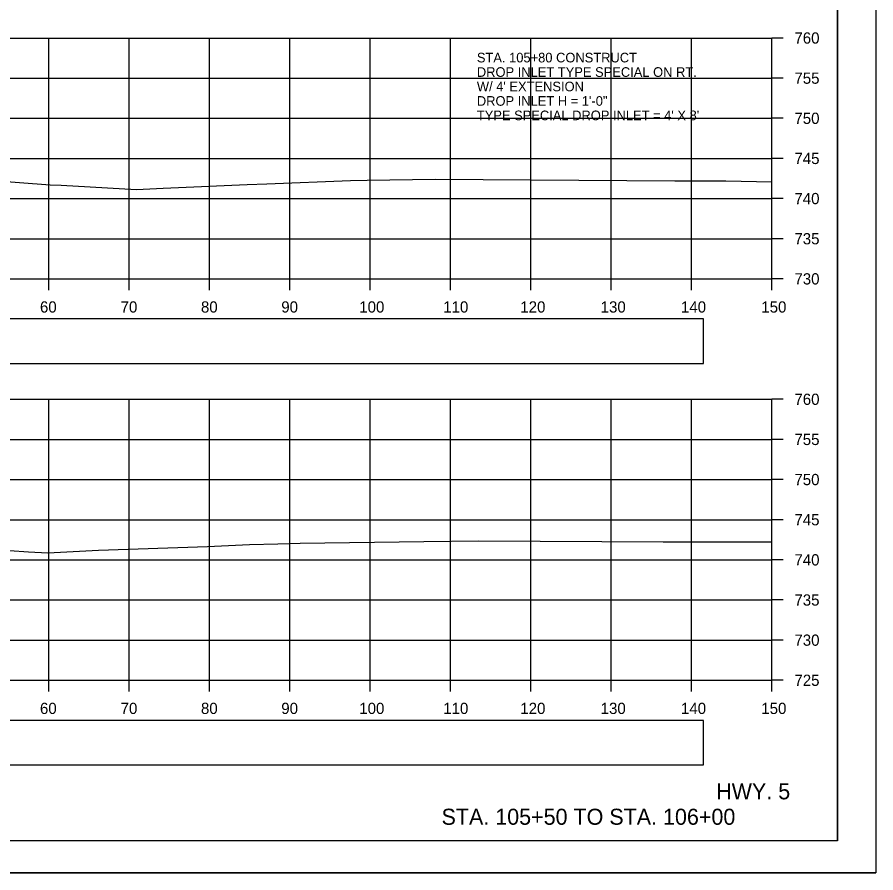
# Model space of a CAD drawing. Extents: x 1202951 to 1376887, y 378065 to 728038.
# Drawn here: x 1376640.7 to 1376747.6, y 379474.5 to 379581.1 of the extents above; entities that cross this region are included whole.
import ezdxf

# ---------------------------------------------------------------- set-up
doc = ezdxf.new("R2010")
doc.units = 0
for name, color, linetype in [('R_Alt Surface', 7, 'Continuous'), ('R_Axis', 7, 'Continuous'), ('R_Axis Annot', 7, 'Continuous'), ('R_Border', 7, 'Continuous'), ('R_Draft', 7, 'Continuous'), ('R_Exist Surface', 7, 'Continuous'), ('R_Grid', 7, 'Continuous'), ('R_No Plot', 7, 'Continuous'), ('R_Water Annot', 7, 'Continuous')]:
    doc.layers.add(name, color=color, linetype=linetype)

msp = doc.modelspace()

# ---------------------------------------------------------------- linework, layer by layer
at = {"layer": 'R_Alt Surface'}
for points in [[(1376615.43, 379537.98), (1376726.14, 379537.98), (1376726.14, 379543.51), (1376615.43, 379543.51)], [(1376615.43, 379487.98), (1376726.14, 379487.98), (1376726.14, 379493.51), (1376615.43, 379493.51)]]:
    msp.add_lwpolyline(points, close=True, dxfattribs=at)
at = {"layer": 'R_Axis'}
for p, q in [((1376734.67, 379548.51), (1376734.67, 379578.51)), ((1376736.07, 379578.51), (1376734.67, 379578.51)), ((1376736.07, 379573.51), (1376734.67, 379573.51)), ((1376736.07, 379568.51), (1376734.67, 379568.51)), ((1376736.07, 379563.51), (1376734.67, 379563.51)), ((1376736.07, 379558.51), (1376734.67, 379558.51)), ((1376736.07, 379553.51), (1376734.67, 379553.51)), ((1376434.67, 379548.51), (1376734.67, 379548.51)), ((1376644.67, 379547.11), (1376644.67, 379548.51)), ((1376654.67, 379547.11), (1376654.67, 379548.51)), ((1376664.67, 379547.11), (1376664.67, 379548.51)), ((1376674.67, 379547.11), (1376674.67, 379548.51)), ((1376684.67, 379547.11), (1376684.67, 379548.51)), ((1376694.67, 379547.11), (1376694.67, 379548.51)), ((1376704.67, 379547.11), (1376704.67, 379548.51)), ((1376714.67, 379547.11), (1376714.67, 379548.51)), ((1376724.67, 379547.11), (1376724.67, 379548.51)), ((1376734.67, 379547.11), (1376734.67, 379548.51)), ((1376736.07, 379548.51), (1376734.67, 379548.51)), ((1376734.67, 379498.51), (1376734.67, 379533.51)), ((1376736.07, 379533.51), (1376734.67, 379533.51)), ((1376736.07, 379528.51), (1376734.67, 379528.51)), ((1376736.07, 379523.51), (1376734.67, 379523.51)), ((1376736.07, 379518.51), (1376734.67, 379518.51)), ((1376736.07, 379513.51), (1376734.67, 379513.51)), ((1376736.07, 379508.51), (1376734.67, 379508.51)), ((1376736.07, 379503.51), (1376734.67, 379503.51)), ((1376434.67, 379498.51), (1376734.67, 379498.51)), ((1376644.67, 379497.11), (1376644.67, 379498.51)), ((1376654.67, 379497.11), (1376654.67, 379498.51)), ((1376664.67, 379497.11), (1376664.67, 379498.51)), ((1376674.67, 379497.11), (1376674.67, 379498.51)), ((1376684.67, 379497.11), (1376684.67, 379498.51)), ((1376694.67, 379497.11), (1376694.67, 379498.51)), ((1376704.67, 379497.11), (1376704.67, 379498.51)), ((1376714.67, 379497.11), (1376714.67, 379498.51)), ((1376724.67, 379497.11), (1376724.67, 379498.51)), ((1376734.67, 379497.11), (1376734.67, 379498.51)), ((1376736.07, 379498.51), (1376734.67, 379498.51))]:
    msp.add_line(p, q, dxfattribs=at)
at = {"layer": 'R_Border'}
for q in [(1376742.85, 379683.97), (1376426.67, 379478.51)]:
    msp.add_line((1376742.85, 379478.51), q, dxfattribs=at)
at = {"layer": 'R_Exist Surface'}
for points in [[(1376636.62, 379560.86), (1376644.84, 379560.23), (1376646.18, 379560.17), (1376655.58, 379559.65), (1376658.89, 379559.79), (1376669.35, 379560.27), (1376671.78, 379560.35), (1376682.21, 379560.78), (1376684.27, 379560.82), (1376692.73, 379560.92), (1376722.57, 379560.73), (1376727.42, 379560.7), (1376728.95, 379560.71), (1376734.67, 379560.58)], [(1376639.74, 379514.67), (1376642.12, 379514.51), (1376644.55, 379514.39), (1376650.83, 379514.7), (1376664.39, 379515.18), (1376669.65, 379515.42), (1376673.17, 379515.52), (1376675.93, 379515.57), (1376691.35, 379515.8), (1376698.2, 379515.88), (1376721.15, 379515.74), (1376727.32, 379515.75), (1376734.67, 379515.75)]]:
    msp.add_lwpolyline(points, dxfattribs=at)
at = {"layer": 'R_Grid'}
for p, q in [((1376434.67, 379578.51), (1376734.67, 379578.51)), ((1376644.67, 379548.51), (1376644.67, 379578.51)), ((1376654.67, 379548.51), (1376654.67, 379578.51)), ((1376664.67, 379548.51), (1376664.67, 379578.51)), ((1376674.67, 379548.51), (1376674.67, 379578.51)), ((1376684.67, 379548.51), (1376684.67, 379578.51)), ((1376694.67, 379548.51), (1376694.67, 379578.51)), ((1376704.67, 379548.51), (1376704.67, 379578.51)), ((1376714.67, 379548.51), (1376714.67, 379578.51)), ((1376724.67, 379548.51), (1376724.67, 379578.51)), ((1376734.67, 379548.51), (1376734.67, 379578.51)), ((1376434.67, 379573.51), (1376734.67, 379573.51)), ((1376434.67, 379568.51), (1376734.67, 379568.51)), ((1376434.67, 379563.51), (1376734.67, 379563.51)), ((1376434.67, 379558.51), (1376734.67, 379558.51)), ((1376434.67, 379553.51), (1376734.67, 379553.51)), ((1376434.67, 379548.51), (1376734.67, 379548.51)), ((1376434.67, 379533.51), (1376734.67, 379533.51)), ((1376644.67, 379498.51), (1376644.67, 379533.51)), ((1376654.67, 379498.51), (1376654.67, 379533.51)), ((1376664.67, 379498.51), (1376664.67, 379533.51)), ((1376674.67, 379498.51), (1376674.67, 379533.51)), ((1376684.67, 379498.51), (1376684.67, 379533.51)), ((1376694.67, 379498.51), (1376694.67, 379533.51)), ((1376704.67, 379498.51), (1376704.67, 379533.51)), ((1376714.67, 379498.51), (1376714.67, 379533.51)), ((1376724.67, 379498.51), (1376724.67, 379533.51)), ((1376734.67, 379498.51), (1376734.67, 379533.51)), ((1376434.67, 379528.51), (1376734.67, 379528.51)), ((1376434.67, 379523.51), (1376734.67, 379523.51)), ((1376434.67, 379518.51), (1376734.67, 379518.51)), ((1376434.67, 379513.51), (1376734.67, 379513.51)), ((1376434.67, 379508.51), (1376734.67, 379508.51)), ((1376434.67, 379503.51), (1376734.67, 379503.51)), ((1376434.67, 379498.51), (1376734.67, 379498.51))]:
    msp.add_line(p, q, dxfattribs=at)
at = {"layer": 'R_No Plot'}
msp.add_line((1376414.27, 379474.53), (1376747.6, 379474.53), dxfattribs=at)
for points in [[(1376414.26, 379687.86), (1376747.6, 379687.86), (1376747.6, 379474.52), (1376414.26, 379474.52)], [(1376660.59, 379683.97), (1376680.21, 379683.97), (1376680.21, 379674.09), (1376696.32, 379674.09), (1376719.52, 379674.09), (1376719.64, 379645.93), (1376742.85, 379645.93), (1376742.85, 379478.51), (1376426.67, 379478.51), (1376426.67, 379683.97)]]:
    msp.add_lwpolyline(points, close=True, dxfattribs=at)

# ---------------------------------------------------------------- texts
at = {"layer": 'R_Axis Annot'}
for s, p in [('760', (1376737.47, 379577.81)), ('755', (1376737.47, 379572.81)), ('750', (1376737.47, 379567.81)), ('745', (1376737.47, 379562.81)), ('740', (1376737.47, 379557.81)), ('735', (1376737.47, 379552.81)), ('730', (1376737.47, 379547.81)), ('60', (1376643.55, 379544.31)), ('70', (1376653.59, 379544.31)), ('80', (1376663.59, 379544.31)), ('90', (1376673.59, 379544.31)), ('100', (1376683.3, 379544.31)), ('110', (1376693.75, 379544.31)), ('120', (1376703.35, 379544.31)), ('130', (1376713.35, 379544.31)), ('140', (1376723.35, 379544.31)), ('150', (1376733.35, 379544.31)), ('760', (1376737.47, 379532.81)), ('755', (1376737.47, 379527.81)), ('750', (1376737.47, 379522.81)), ('745', (1376737.47, 379517.81)), ('740', (1376737.47, 379512.81)), ('735', (1376737.47, 379507.81)), ('730', (1376737.47, 379502.81)), ('725', (1376737.47, 379497.81)), ('60', (1376643.55, 379494.31)), ('70', (1376653.59, 379494.31)), ('80', (1376663.59, 379494.31)), ('90', (1376673.59, 379494.31)), ('100', (1376683.3, 379494.31)), ('110', (1376693.75, 379494.31)), ('120', (1376703.35, 379494.31)), ('130', (1376713.35, 379494.31)), ('140', (1376723.35, 379494.31)), ('150', (1376733.35, 379494.31))]:
    msp.add_text(s, height=1.4, dxfattribs=at).set_placement(p)
at = {"layer": 'R_Draft'}
for s, p in [('HWY. 5', (1376727.73, 379483.68)), ('STA. 105+50 TO STA. 106+00', (1376693.54, 379480.51))]:
    msp.add_text(s, height=2, dxfattribs=at).set_placement(p)
at = {"layer": 'R_Water Annot'}
for s, p in [('STA. 105+80 CONSTRUCT', (1376697.94, 379575.47)), ('DROP INLET TYPE SPECIAL ON RT.', (1376697.94, 379573.67)), ("W/ 4' EXTENSION", (1376697.94, 379571.87)), ('DROP INLET H = 1\'-0"', (1376697.94, 379570.07)), ("TYPE SPECIAL DROP INLET = 4' X 8'", (1376697.94, 379568.27))]:
    msp.add_text(s, height=1.2, dxfattribs=at).set_placement(p)

doc.saveas('drawing.dxf')
